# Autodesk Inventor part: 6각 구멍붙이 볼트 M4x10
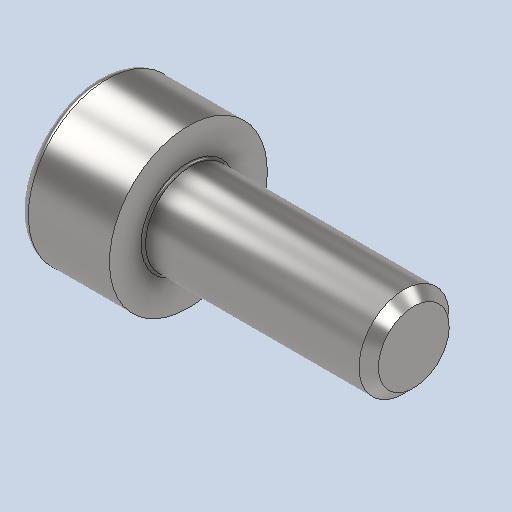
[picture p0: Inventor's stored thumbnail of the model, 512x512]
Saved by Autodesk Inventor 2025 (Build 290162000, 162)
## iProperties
Created: 2026-07
Part Number: 6각 구멍붙이 볼트 M4x10
Material: 강철, 연강
Description: 6각머리 태핑 나사
Document SubType Name: Modeling
Designer: KDI
Density: 7.86 g/cm^3
Appearance: 기본값
Author: jhkim
Revision Number: 1
Sending System: Autodesk Inventor 2027
Preprocessor: ST-DEVELOPER v20.1
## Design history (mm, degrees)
feature "Solid1"
node "솔리드1"
